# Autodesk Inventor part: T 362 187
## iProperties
Created: 2005-12
Part Number: T 362 187
Material: Durethan BKV30H
Document SubType Name: Modeling
Designer: I.Baliuc
Manufacturer: Standard
Standards Organization: Custom
Description: Hebel
Density: 0.94 g/cm^3
Title: Hebel
Company: Mayer & Müller AG Schaltgeräte
Zweck: Schaltwelle LH
Author: T.Messerschmitt
Keywords: 213549
Revision Number: 362187
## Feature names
1. Extrusion2
2. Bohrung1 [Hole]
3. Extrusion3
4. Extrusion4
5. Rechteckige Anordnung1 [Rectangular Pattern]
6. Bohrung_Ø4.1 [Hole]
7. Extrusion5
